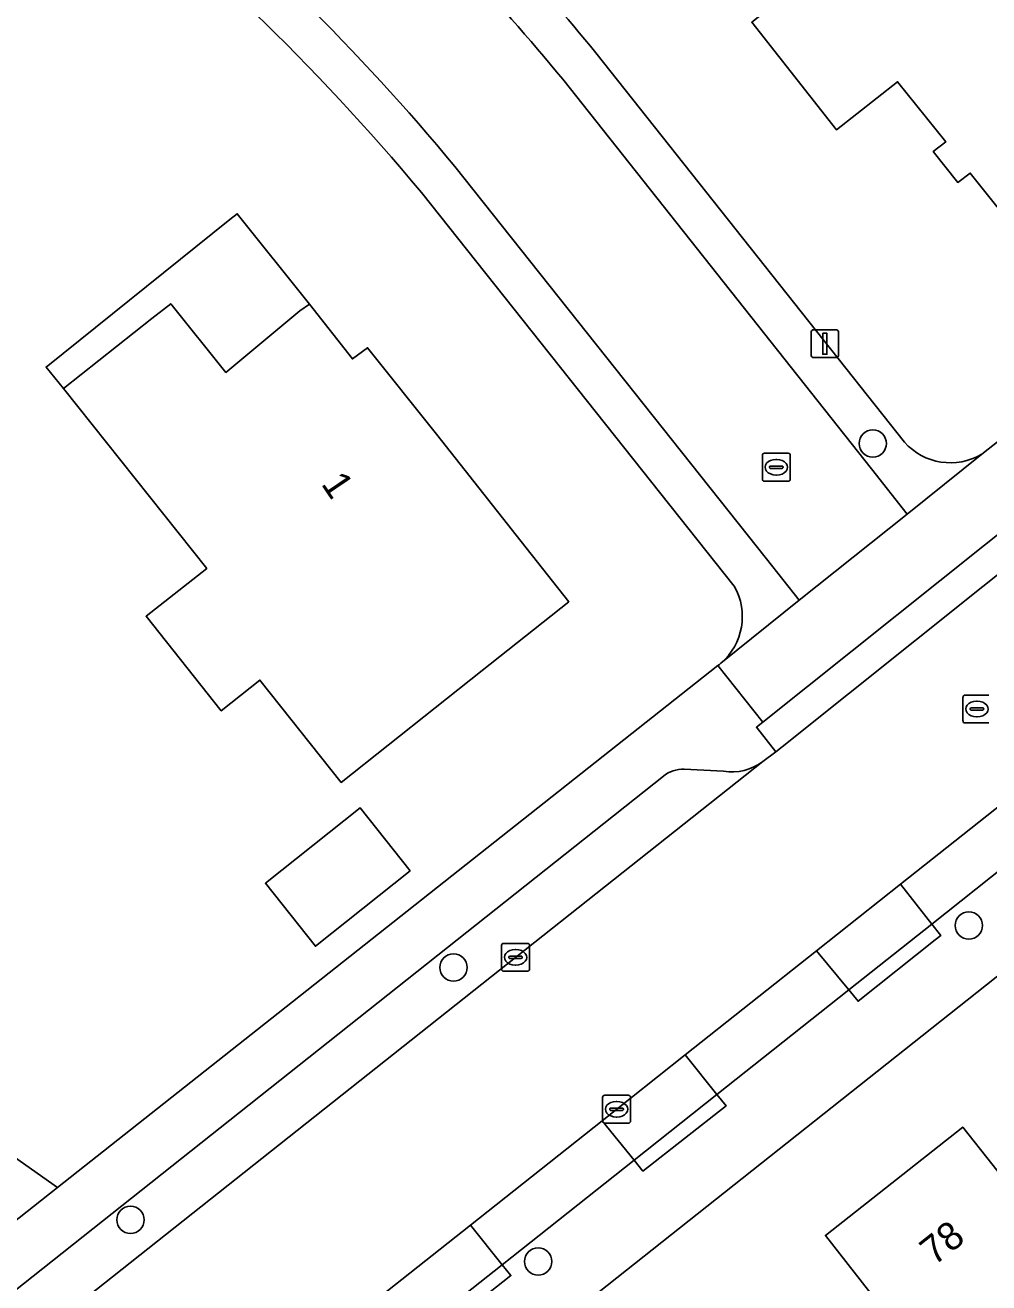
# Model space of a CAD drawing. Extents: x 159626 to 160723, y 388173 to 389416.
# Drawn here: x 160116.73 to 160151.28, y 388698.64 to 388743.72 of the extents above; entities that cross this region are included whole.
import ezdxf

# ---------------------------------------------------------------- set-up
doc = ezdxf.new("R2010")
doc.units = 0
for name, color, linetype in [('IMGEO_Boom', 7, 'Continuous'), ('IMGEO_Erf', 7, 'Continuous'), ('IMGEO_Houtwal', 7, 'Continuous'), ('IMGEO_Kolk', 7, 'Continuous'), ('IMGEO_Lichtmast', 7, 'Continuous'), ('IMGEO_Pand', 7, 'Continuous'), ('IMGEO_Pand_nummerreeks', 7, 'Continuous'), ('IMGEO_Pand_overbouw', 7, 'Continuous'), ('IMGEO_Parkeervlak_open', 7, 'Continuous'), ('IMGEO_Rijbaan_lokaal_gesloten', 7, 'Continuous'), ('IMGEO_Rijbaan_lokaal_open', 7, 'Continuous'), ('IMGEO_Rioolput', 7, 'Continuous'), ('IMGEO_Voetpad_open', 7, 'Continuous')]:
    doc.layers.add(name, color=color, linetype=linetype)

msp = doc.modelspace()

# ---------------------------------------------------------------- linework, layer by layer
at = {"layer": 'IMGEO_Boom'}
for centre in [(160147.12, 388728.723), (160150.563, 388711.45), (160132.088, 388709.944), (160120.509, 388700.9), (160135.123, 388699.407)]:
    msp.add_circle(centre, 0.489, dxfattribs=at)
at = {"layer": 'IMGEO_Erf'}
for points in [[(160014.595, 388792.981), (160040.756, 388771.171), (160054.83, 388758.93), (160059.19, 388755.976), (160057.971, 388757.499), (160060.57, 388759.58), (160063.15, 388756.358), (160061.077, 388754.698), (160070.24, 388748.49), (160100.703, 388726.492), (160106.44, 388731.18), (160113.279, 388736.768), (160115.679, 388733.752), (160110.89, 388730), (160103.729, 388724.39), (160096.772, 388718.94), (160098.468, 388716.143), (160111.625, 388706.461), (160117.888, 388702.055), (160125.808, 388708.311), (160141.571, 388720.763), (160141.623, 388720.804), (160141.674, 388720.846)], [(160137.195, 388742.726), (160148.258, 388728.772)], [(160151.026, 388728.336), (160165.29, 388739.573)], [(160142.156, 388723.604), (160130.943, 388737.717)], [(160173.521, 388727.014), (160150.851, 388709.051), (160094.032, 388664.03)], [(160147.482, 388697.708), (160145.424, 388700.34), (160150.347, 388704.22), (160152.434, 388701.586), (160153.246, 388700.562), (160155.931, 388702.705), (160155.122, 388703.722), (160153.013, 388706.376), (160157.936, 388710.263), (160160.019, 388707.635), (160160.827, 388706.615), (160163.526, 388708.77), (160162.742, 388709.77), (160160.664, 388712.422), (160165.531, 388716.284), (160167.648, 388713.617), (160168.403, 388712.664), (160171.055, 388714.781), (160170.342, 388715.731), (160168.238, 388718.412), (160173.228, 388722.373), (160175.355, 388719.746), (160179.715, 388723.147), (160185.44, 388721.912)]]:
    msp.add_lwpolyline(points, dxfattribs=at)
for points in [[(160150.591, 388750), (160154.519, 388753.109), (160156.98, 388750), (160161.683, 388744.057), (160157.95, 388741.385), (160156.726, 388740.509), (160157.27, 388739.782), (160152.532, 388736.005), (160150.616, 388738.417), (160150.166, 388738.08), (160149.286, 388739.183), (160149.734, 388739.532), (160148.008, 388741.687), (160145.817, 388739.968), (160142.781, 388743.819)], [(160121.278, 388733.199), (160121.955, 388733.734), (160123.933, 388731.271), (160126.585, 388733.476), (160126.93, 388733.712), (160128.463, 388731.753), (160129.01, 388732.154), (160131.478, 388729.06), (160134.517, 388725.21), (160136.224, 388723.048), (160133.116, 388720.582), (160128.066, 388716.575), (160125.15, 388720.244), (160123.76, 388719.14), (160121.07, 388722.53), (160123.243, 388724.245), (160118.111, 388730.695)], [(160130.538, 388713.404), (160127.137, 388710.705), (160125.345, 388712.963), (160128.747, 388715.662)]]:
    msp.add_lwpolyline(points, close=True, dxfattribs=at)
for centre, radius, start, end in [((160068.487, 388685.621), 81.331, 39.83222, 52.33222), ((160071.892, 388689.017), 84.552, 39.43592, 46.15732), ((160149.907, 388730.237), 2.206, 221.6166, 300.4807), ((160140.242, 388722.517), 2.201, 310.5889, 29.5848)]:
    msp.add_arc(centre, radius, start, end, dxfattribs=at)
at = {"layer": 'IMGEO_Houtwal'}
msp.add_lwpolyline([(160044.194, 388729.267), (160035.207, 388725.196), (160035.26, 388724.75), (160036.739, 388724.533), (160038.232, 388724.113), (160039.808, 388723.459), (160042.173, 388721.999), (160044.118, 388720.119), (160078.58, 388677.212), (160081.232, 388676.573), (160112.511, 388700.291), (160113.699, 388698.746), (160117.888, 388702.055), (160111.625, 388706.461), (160103.114, 388700.48), (160082.042, 388685.672)], close=True, dxfattribs=at)
at = {"layer": 'IMGEO_Kolk'}
for p, q in [((160143.162, 388727.446), (160143.162, 388728.298)), ((160143.237, 388728.372), (160144.089, 388728.372)), ((160143.65, 388728.152), (160143.675, 388728.152)), ((160144.163, 388728.298), (160144.163, 388727.446)), ((160143.421, 388727.866), (160143.421, 388727.878)), ((160143.859, 388727.829), (160143.461, 388727.829)), ((160143.464, 388727.915), (160143.862, 388727.915)), ((160143.673, 388727.592), (160143.648, 388727.592)), ((160143.905, 388727.878), (160143.905, 388727.866)), ((160144.089, 388727.372), (160143.237, 388727.372)), ((160133.813, 388709.881), (160133.813, 388710.733)), ((160133.888, 388710.807), (160134.74, 388710.807)), ((160134.301, 388710.587), (160134.326, 388710.587)), ((160134.814, 388710.733), (160134.814, 388709.881)), ((160134.072, 388710.301), (160134.072, 388710.313)), ((160134.51, 388710.264), (160134.112, 388710.264)), ((160134.115, 388710.35), (160134.513, 388710.35)), ((160134.324, 388710.027), (160134.299, 388710.027)), ((160134.556, 388710.313), (160134.556, 388710.301)), ((160134.74, 388709.807), (160133.888, 388709.807)), ((160137.436, 388704.436), (160137.436, 388705.288)), ((160137.511, 388705.362), (160138.363, 388705.362)), ((160137.924, 388705.142), (160137.949, 388705.142)), ((160138.437, 388705.288), (160138.437, 388704.436)), ((160137.695, 388704.856), (160137.695, 388704.868)), ((160138.133, 388704.819), (160137.735, 388704.819)), ((160137.738, 388704.905), (160138.136, 388704.905)), ((160137.947, 388704.582), (160137.922, 388704.582)), ((160138.179, 388704.868), (160138.179, 388704.856)), ((160138.363, 388704.362), (160137.511, 388704.362))]:
    msp.add_line(p, q, dxfattribs=at)
for points in [[(160143.162, 388727.446), (160143.162, 388728.298)], [(160143.237, 388728.372), (160144.089, 388728.372)], [(160144.163, 388728.298), (160144.163, 388727.446)], [(160144.089, 388727.372), (160143.237, 388727.372)], [(160133.813, 388709.881), (160133.813, 388710.733)], [(160133.888, 388710.807), (160134.74, 388710.807)], [(160134.814, 388710.733), (160134.814, 388709.881)], [(160134.74, 388709.807), (160133.888, 388709.807)], [(160137.436, 388704.436), (160137.436, 388705.288)], [(160137.511, 388705.362), (160138.363, 388705.362)], [(160138.437, 388705.288), (160138.437, 388704.436)], [(160138.363, 388704.362), (160137.511, 388704.362)]]:
    msp.add_lwpolyline(points, dxfattribs=at)
for centre, radius, start, end in [((160143.239, 388728.296), 0.0765, 91.552, 178.448), ((160143.239, 388728.296), 0.0765, 91.552, 178.448), ((160144.087, 388728.296), 0.0765, 1.552, 88.448), ((160144.087, 388728.296), 0.0765, 1.552, 88.448), ((160143.461, 388727.875), 0.0403, 85.8775, 175.7526), ((160143.458, 388727.865), 0.0366, 178.938, 274.7102), ((160143.862, 388727.872), 0.043, 264.8664, 352.4533), ((160143.866, 388727.877), 0.0386, 1.7309, 96.639), ((160143.239, 388727.448), 0.0765, 181.552, 268.448), ((160143.239, 388727.448), 0.0765, 181.552, 268.448), ((160144.087, 388727.448), 0.0765, 271.552, 358.448), ((160144.087, 388727.448), 0.0765, 271.552, 358.448), ((160133.89, 388710.731), 0.0765, 91.552, 178.448), ((160133.89, 388710.731), 0.0765, 91.552, 178.448), ((160134.738, 388710.731), 0.0765, 1.552, 88.448), ((160134.738, 388710.731), 0.0765, 1.552, 88.448), ((160134.112, 388710.31), 0.0403, 85.8775, 175.7526), ((160134.109, 388710.3), 0.0366, 178.938, 274.7102), ((160134.513, 388710.307), 0.043, 264.8664, 352.4533), ((160134.517, 388710.312), 0.0386, 1.7309, 96.639), ((160133.89, 388709.883), 0.0765, 181.552, 268.448), ((160133.89, 388709.883), 0.0765, 181.552, 268.448), ((160134.738, 388709.883), 0.0765, 271.552, 358.448), ((160134.738, 388709.883), 0.0765, 271.552, 358.448), ((160137.513, 388705.286), 0.0765, 91.552, 178.448), ((160137.513, 388705.286), 0.0765, 91.552, 178.448), ((160138.361, 388705.286), 0.0765, 1.552, 88.448), ((160138.361, 388705.286), 0.0765, 1.552, 88.448), ((160137.735, 388704.865), 0.0403, 85.8775, 175.7526), ((160137.732, 388704.855), 0.0366, 178.938, 274.7102), ((160138.136, 388704.862), 0.043, 264.8664, 352.4533), ((160138.14, 388704.867), 0.0386, 1.7309, 96.639), ((160137.513, 388704.438), 0.0765, 181.552, 268.448), ((160137.513, 388704.438), 0.0765, 181.552, 268.448), ((160138.361, 388704.438), 0.0765, 271.552, 358.448), ((160138.361, 388704.438), 0.0765, 271.552, 358.448)]:
    msp.add_arc(centre, radius, start, end, dxfattribs=at)
for centre, major_axis, ratio, start_param, end_param in [((160143.649, 388727.872), (-0.387, 0.002), 0.722429, 4.712389, 7.853982), ((160143.674, 388727.872), (-0.39, 0.002), 0.717154, 1.570796, 4.712389), ((160134.3, 388710.307), (-0.387, 0.002), 0.722429, 4.712389, 7.853982), ((160134.325, 388710.307), (-0.39, 0.002), 0.717154, 1.570796, 4.712389), ((160137.923, 388704.862), (-0.387, 0.002), 0.722429, 4.712389, 7.853982), ((160137.948, 388704.862), (-0.39, 0.002), 0.717154, 1.570796, 4.712389)]:
    msp.add_ellipse(centre, major_axis=major_axis, ratio=ratio, start_param=start_param, end_param=end_param, dxfattribs=at)
at = {"layer": 'IMGEO_Lichtmast'}
for p, q in [((160144.907, 388731.899), (160144.907, 388732.699)), ((160144.907, 388732.699), (160144.907, 388731.899)), ((160145.007, 388732.799), (160145.797, 388732.799)), ((160145.797, 388732.799), (160145.007, 388732.799)), ((160145.897, 388732.699), (160145.897, 388731.899)), ((160145.897, 388731.899), (160145.897, 388732.699)), ((160145.797, 388731.799), (160145.007, 388731.799)), ((160145.007, 388731.799), (160145.797, 388731.799))]:
    msp.add_line(p, q, dxfattribs=at)
msp.add_lwpolyline([(160145.327, 388732.674), (160145.477, 388732.674), (160145.477, 388731.924), (160145.327, 388731.924), (160145.327, 388732.674)], dxfattribs=at)
for centre, start, end in [((160145.007, 388732.699), 90, 180), ((160145.007, 388732.699), 90, 180), ((160145.797, 388732.699), 0, 90), ((160145.797, 388732.699), 360, 90), ((160145.007, 388731.899), 180, 270), ((160145.007, 388731.899), 180, 270), ((160145.797, 388731.899), 270, 0), ((160145.797, 388731.899), 270, 0)]:
    msp.add_arc(centre, 0.1, start, end, dxfattribs=at)
at = {"layer": 'IMGEO_Pand'}
for points in [[(160157.27, 388739.782), (160156.726, 388740.509), (160157.95, 388741.385), (160161.683, 388744.057), (160156.98, 388750), (160154.519, 388753.109), (160150.591, 388750), (160142.781, 388743.819), (160145.817, 388739.968), (160148.008, 388741.687), (160149.734, 388739.532), (160149.286, 388739.183), (160150.166, 388738.08), (160150.616, 388738.417), (160152.532, 388736.005)], [(160133.116, 388720.582), (160136.224, 388723.048), (160134.517, 388725.21), (160131.478, 388729.06), (160129.01, 388732.154), (160128.463, 388731.753), (160126.93, 388733.712), (160126.585, 388733.476), (160123.933, 388731.271), (160121.955, 388733.734), (160121.278, 388733.199), (160118.111, 388730.695), (160123.243, 388724.245), (160121.07, 388722.53), (160123.76, 388719.14), (160125.15, 388720.244), (160128.066, 388716.575)], [(160130.538, 388713.404), (160128.747, 388715.662), (160125.345, 388712.963), (160127.137, 388710.705)], [(160153.246, 388700.562), (160152.434, 388701.586), (160150.347, 388704.22), (160145.424, 388700.34), (160147.482, 388697.708), (160147.512, 388697.732), (160148.336, 388696.642), (160145.666, 388694.509), (160150.424, 388688.507), (160155.01, 388692.139), (160153.513, 388694.028), (160156.414, 388696.325), (160156.531, 388696.418)]]:
    msp.add_lwpolyline(points, close=True, dxfattribs=at)
at = {"layer": 'IMGEO_Pand_overbouw'}
msp.add_lwpolyline([(160126.93, 388733.712), (160124.338, 388736.958), (160124.074, 388736.746), (160117.486, 388731.459), (160118.111, 388730.695), (160121.278, 388733.199), (160121.955, 388733.734), (160123.933, 388731.271), (160126.585, 388733.476)], close=True, dxfattribs=at)
at = {"layer": 'IMGEO_Parkeervlak_open'}
for points in [[(160085.885, 388671.953), (160143.177, 388717.325)], [(160139.612, 388716.804), (160087.01, 388675.096), (160086.793, 388674.715), (160086.598, 388673.317)], [(160141.772, 388716.983), (160140.358, 388717.046)]]:
    msp.add_lwpolyline(points, dxfattribs=at)
for points in [[(160153.975, 388715.258), (160152.872, 388716.695), (160148.116, 388712.927), (160149.234, 388711.499)], [(160149.234, 388711.499), (160148.116, 388712.927), (160145.108, 388710.543), (160146.258, 388709.139)], [(160146.258, 388709.139), (160145.108, 388710.543), (160140.4, 388706.812), (160141.535, 388705.394)], [(160141.535, 388705.394), (160140.4, 388706.812), (160137.417, 388704.448), (160138.561, 388703.035)], [(160138.561, 388703.035), (160137.417, 388704.448), (160132.7, 388700.709), (160133.838, 388699.29)], [(160133.838, 388699.29), (160132.7, 388700.709), (160129.729, 388698.354), (160130.859, 388696.928)]]:
    msp.add_lwpolyline(points, close=True, dxfattribs=at)
for centre, radius, start, end in [((160142.084, 388718.76), 1.804, 260.0533, 307.3081), ((160140.311, 388715.921), 1.126, 87.5834, 128.3624)]:
    msp.add_arc(centre, radius, start, end, dxfattribs=at)
at = {"layer": 'IMGEO_Rijbaan_lokaal_gesloten'}
for points in [[(160167.383, 388736.528), (160164.446, 388734.198), (160154.322, 388726.169), (160153.45, 388725.499), (160143.876, 388717.854), (160143.646, 388717.671), (160143.177, 388717.325), (160085.885, 388671.953), (160085.177, 388671.383), (160084.775, 388671.059), (160074.107, 388662.597), (160068.619, 388658.215), (160050.132, 388643.587), (160047.169, 388641.243), (160035.367, 388631.905), (160032.398, 388629.556), (160020.566, 388620.194), (160017.62, 388617.863), (160009.366, 388611.332), (160008.998, 388611.041), (160000, 388603.924), (159995.738, 388600.553), (159983.064, 388590.517)], [(160076.921, 388656.375), (160090.898, 388667.506), (160104.695, 388678.512), (160114.92, 388686.617), (160117.817, 388688.912), (160122.521, 388692.641), (160125.504, 388695.005), (160129.729, 388698.354), (160132.7, 388700.709), (160137.417, 388704.448), (160140.4, 388706.812), (160145.108, 388710.543), (160148.116, 388712.927), (160152.872, 388716.695), (160155.799, 388719.014), (160160.515, 388722.751), (160163.509, 388725.123), (160170.527, 388730.683), (160171.328, 388731.319)]]:
    msp.add_lwpolyline(points, dxfattribs=at)
at = {"layer": 'IMGEO_Rijbaan_lokaal_open'}
msp.add_lwpolyline([(160132.142, 388738.649), (160143.312, 388724.59), (160144.483, 388723.108), (160148.356, 388726.193), (160147.076, 388727.819), (160136.012, 388741.776)], dxfattribs=at)
for centre, radius, start, end in [((160068.879, 388686.116), 82.231, 39.706, 50.97639), ((160070.578, 388687.681), 84.899, 39.58107, 47.22591)]:
    msp.add_arc(centre, radius, start, end, dxfattribs=at)
at = {"layer": 'IMGEO_Rioolput'}
for p, q in [((160150.355, 388718.78), (160150.355, 388719.632)), ((160150.43, 388719.706), (160151.282, 388719.706)), ((160150.843, 388719.486), (160150.868, 388719.486)), ((160150.614, 388719.2), (160150.614, 388719.212)), ((160151.052, 388719.163), (160150.654, 388719.163)), ((160150.657, 388719.249), (160151.055, 388719.249)), ((160151.098, 388719.212), (160151.098, 388719.2)), ((160151.282, 388718.706), (160150.43, 388718.706)), ((160150.866, 388718.926), (160150.841, 388718.926))]:
    msp.add_line(p, q, dxfattribs=at)
for points in [[(160150.355, 388718.78), (160150.355, 388719.632)], [(160150.43, 388719.706), (160151.282, 388719.706)], [(160151.282, 388718.706), (160150.43, 388718.706)]]:
    msp.add_lwpolyline(points, dxfattribs=at)
for centre, radius, start, end in [((160150.432, 388719.63), 0.0765, 91.552, 178.448), ((160150.432, 388719.63), 0.0765, 91.552, 178.448), ((160150.654, 388719.209), 0.0403, 85.8775, 175.7526), ((160150.651, 388719.199), 0.0366, 178.938, 274.7102), ((160151.055, 388719.206), 0.043, 264.8664, 352.4533), ((160151.059, 388719.211), 0.0386, 1.7309, 96.639), ((160150.432, 388718.782), 0.0765, 181.552, 268.448), ((160150.432, 388718.782), 0.0765, 181.552, 268.448)]:
    msp.add_arc(centre, radius, start, end, dxfattribs=at)
for centre, major_axis, ratio, start_param, end_param in [((160150.842, 388719.206), (-0.387, 0.002), 0.722429, 4.712389, 7.853982), ((160150.867, 388719.206), (-0.39, 0.002), 0.717154, 1.570796, 4.712389)]:
    msp.add_ellipse(centre, major_axis=major_axis, ratio=ratio, start_param=start_param, end_param=end_param, dxfattribs=at)
at = {"layer": 'IMGEO_Voetpad_open'}
for points in [[(160148.258, 388728.772), (160137.195, 388742.726)], [(160136.012, 388741.776), (160147.076, 388727.819), (160148.356, 388726.193), (160151.026, 388728.336)], [(160165.29, 388739.573), (160151.026, 388728.336), (160148.356, 388726.193), (160144.483, 388723.108), (160141.674, 388720.846), (160141.623, 388720.804), (160141.571, 388720.763), (160143.176, 388718.737), (160152.726, 388726.356), (160153.45, 388725.499), (160154.322, 388726.169)], [(160141.674, 388720.846), (160144.483, 388723.108), (160143.312, 388724.59), (160132.142, 388738.649)], [(160130.943, 388737.717), (160142.156, 388723.604)], [(160171.673, 388729.291), (160164.631, 388723.707), (160164.937, 388723.291), (160161.984, 388720.933), (160161.651, 388721.344), (160156.924, 388717.596), (160157.256, 388717.174), (160154.299, 388714.833), (160153.975, 388715.258), (160149.234, 388711.499), (160149.555, 388711.088), (160149.36, 388710.933), (160146.591, 388708.735), (160146.258, 388709.139), (160141.535, 388705.394), (160141.859, 388704.99), (160138.878, 388702.645), (160138.561, 388703.035), (160133.838, 388699.29), (160134.15, 388698.902), (160131.172, 388696.547)], [(160089.067, 388660.444), (160094.032, 388664.03), (160150.851, 388709.051), (160173.521, 388727.014)], [(160143.177, 388717.325), (160143.646, 388717.671), (160142.947, 388718.554), (160143.176, 388718.737), (160141.571, 388720.763), (160125.808, 388708.311), (160117.888, 388702.055), (160113.699, 388698.746), (160083.013, 388674.507), (160080.75, 388672.717)], [(160086.598, 388673.317), (160086.793, 388674.715), (160087.01, 388675.096), (160139.612, 388716.804)], [(160140.358, 388717.046), (160141.772, 388716.983)]]:
    msp.add_lwpolyline(points, dxfattribs=at)
for points in [[(160143.876, 388717.854), (160153.45, 388725.499), (160152.726, 388726.356), (160143.176, 388718.737), (160142.947, 388718.554), (160143.646, 388717.671)], [(160149.234, 388711.499), (160146.258, 388709.139), (160146.591, 388708.735), (160149.36, 388710.933), (160149.555, 388711.088)], [(160141.535, 388705.394), (160138.561, 388703.035), (160138.878, 388702.645), (160141.859, 388704.99)], [(160133.838, 388699.29), (160130.859, 388696.928), (160131.172, 388696.547), (160134.15, 388698.902)]]:
    msp.add_lwpolyline(points, close=True, dxfattribs=at)
for centre, radius, start, end in [((160068.487, 388685.621), 81.331, 39.83222, 52.33222), ((160068.879, 388686.116), 82.231, 39.706, 50.97639), ((160070.578, 388687.681), 84.899, 39.58107, 47.22591), ((160071.892, 388689.017), 84.552, 39.43592, 46.15732), ((160149.907, 388730.237), 2.206, 221.6166, 300.4807), ((160140.242, 388722.517), 2.201, 310.5889, 29.5848), ((160142.084, 388718.76), 1.804, 260.0533, 307.3081), ((160140.311, 388715.921), 1.126, 87.5834, 128.3624)]:
    msp.add_arc(centre, radius, start, end, dxfattribs=at)

# ---------------------------------------------------------------- texts
at = {"layer": 'IMGEO_Pand_nummerreeks'}
for s, rotation, p in [('1', 304.0599, (160127.322, 388727.275)), ('78', 38.2449, (160149.322, 388699.235))]:
    msp.add_text(s, height=1, rotation=rotation, dxfattribs=at).set_placement(p)

doc.saveas('drawing.dxf')
